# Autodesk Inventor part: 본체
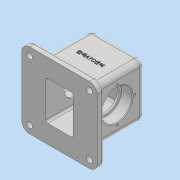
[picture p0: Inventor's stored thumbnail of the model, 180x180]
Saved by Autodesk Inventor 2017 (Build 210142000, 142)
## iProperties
Part Number: 본체
Material: 일반
Document SubType Name: Modeling
Designer: MRC
Density: 1 g/cm^3
Appearance: 기본값
Mass: 392.441 g
Surface Area: 723.029 cm^2
Volume: 392.441 cm^3
Author: MRC
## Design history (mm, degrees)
sketch "스케치1"
  geometry: L1 (-41, 41)-(41, 41); L2 (41, 41)-(41, -41); L3 (41, -41)-(-41, -41); L4 (-41, -41)-(-41, 41); L5 (-41, 41)-(41, -41); L6 (41, 41)-(-41, -41); 1 further point
  constraints: 12 end point, 2 midpoint, 2 parallel, 1 horizontal, 1 perpendicular
  dimensions: "d0" = 82 distance of L2.end L3.end; "d1" = 82 distance of L1.end L2.end
extrude "돌출1" new body sketch "스케치1" distance "d2" = 42; taper "d3" = 0 deg; dims "d67" = 38, "d68" = 0
sketch "스케치2"
  geometry: C1 r 23.5 at (-41, 38); 1 further point
  constraints: 1 centre point, 1 coincident
  dimensions: "d4" = 23.5 radius of C1
extrude "돌출2" cut sketch "스케치2" distance "d5" = 17; taper "d6" = 0 deg
sketch "스케치3"
  geometry: C1 r 20 at (0, 0); 1 further point
  constraints: 1 centre point, 1 coincident
  dimensions: "d7" = 20 radius of C1
extrude "돌출3" cut sketch "스케치3" distance "d8" = 3; taper "d9" = 0 deg
sketch "스케치4"
  geometry: 2 further points
  constraints: 1 vertical alignment
  dimensions: "d10" = 27 distance of point (-41, 38) point (-41, 65)
hole "구멍1" sketch "스케치4" at (-41, 65) diameter "d11" = 3.242; stored, may be unused: countersink angle "d15" = 90 deg, drill point angle "d17" = 118 deg; dims "d12" = 8, "d13" = 4, "d14" = 2, "d16" = 11.8
sketch "스케치6"
  geometry: L1 (-58, -58)-(58, -58); L2 (58, -58)-(58, 58); L3 (58, 58)-(-58, 58); L4 (-58, 58)-(-58, -58); L5 (-58, -58)-(58, 58); L6 (58, -58)-(-58, 58); 1 further point
  constraints: 12 end point, 2 midpoint, 2 parallel, 1 horizontal, 1 perpendicular
  dimensions: "d23" = 116 distance of L3.end L2.end; "d24" = 116 distance of L2.end L1.end
extrude "돌출4" join sketch "스케치6" distance "d25" = 10; taper "d26" = 0 deg
sketch "스케치7"
  geometry: L1 (21, -30)-(-21, -30); L2 (-21, -30)-(-21, 30); L3 (-21, 30)-(21, 30); L4 (21, 30)-(21, -30); L5 (21, -30)-(-21, 30); L6 (-21, -30)-(21, 30); 1 further point
  constraints: 12 end point, 2 midpoint, 2 parallel, 1 horizontal, 1 perpendicular
  dimensions: "d27" = 42 distance of L2.end L3.end; "d28" = 60 distance of L1.end L2.end
extrude "돌출5" cut sketch "스케치7" distance "d29" = 80; taper "d30" = 0 deg
sketch "스케치8"
  geometry: C1 r 7.5 at (0, 0); 1 further point
  constraints: 1 centre point, 1 coincident
  dimensions: "d31" = 7.5 radius of C1
extrude "돌출6" join sketch "스케치8" distance "d32" = 4; taper "d33" = 0 deg
sketch "스케치9"
  geometry: 1 further point
hole "구멍2" sketch "스케치9" at (0, 0) diameter "d34" = 4.917; stored, may be unused: countersink angle "d38" = 90 deg, drill point angle "d40" = 118 deg; dims "d35" = 20, "d36" = 4, "d37" = 2, "d39" = 17.1
fillet "모깎기1" dims "d41" = 8
fillet "모깎기2" dims "d42" = 8
fillet "모깎기3" dims "d43" = 3
fillet "모깎기4" dims "d44" = 12
fillet "모깎기5" dims "d45" = 3
fillet "모깎기6" dims "d46" = 3
sketch "스케치10"
  geometry: C1 r 4.5 at (-46, 46); A1 r 12 centre (-46, 46) between (-46, 58) and (-58, 46) reference; 1 further point
  constraints: 1 centre point, 1 coincident
  dimensions: "d47" = 4.5 radius of C1
extrude "돌출7" cut sketch "스케치10" stored distance "d48" = 4; taper "d49" = 0 deg
chamfer "모따기1" distance "d50" = 1; stored, may be unused: second distance "d51" = 2, angle "d52" = 45 deg
chamfer "모따기2" distance "d53" = 1; stored, may be unused: second distance "d54" = 2, angle "d55" = 45 deg
chamfer "모따기3" distance "d56" = 0.6; stored, may be unused: second distance "d57" = 2, angle "d58" = 45 deg
chamfer "모따기4" distance "d59" = 0.6; stored, may be unused: second distance "d60" = 2, angle "d61" = 45 deg
fillet "모깎기7" dims "d62" = 3
fillet "모깎기8" dims "d63" = 3
sketch "스케치11"
  geometry: L1 (79, -82)-(-13, -82) reference; 2 further points
  constraints: 1 coincident, 1 other
  dimensions: "d64" = 48 distance from line of L1 point (33, -34)
feature "엠보싱1" sketch "스케치11" dims "d0" = 82, "d1" = 82, "d11" = 3.242, "d65" = 0.5, "d66" = 0
node "솔리드1"
pattern_circular "원형 패턴1" dims angle "d19" = 360 deg
mirror "미러1"
mirror "미러2"
mirror "미러3"
